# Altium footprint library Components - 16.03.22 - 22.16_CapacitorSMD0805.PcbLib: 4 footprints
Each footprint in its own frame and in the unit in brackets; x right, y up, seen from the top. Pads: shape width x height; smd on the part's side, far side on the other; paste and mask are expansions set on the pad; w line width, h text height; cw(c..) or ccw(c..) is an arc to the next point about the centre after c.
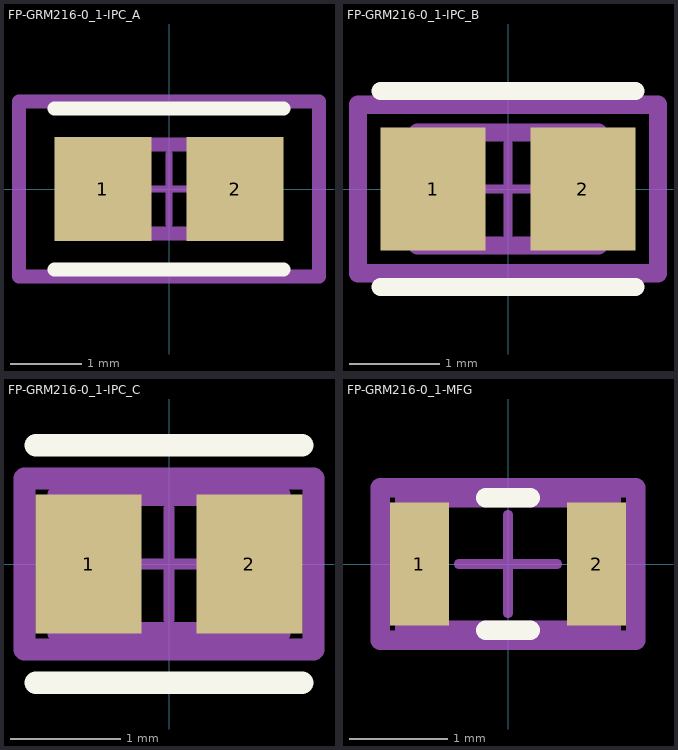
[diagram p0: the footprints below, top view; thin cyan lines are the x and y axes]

## FP-GRM216-0_1-IPC_A [mm]
pads (2):
  rect 1.358x1.461 smd paste+0 mask+0: 1(-0.927,0) 2(0.927,0)
Top Overlay:
  lines w0.2: -1.606,-1.13 1.606,-1.13 ; -1.606,1.13 1.606,1.13
Top Assembly:
  lines w0.2: -2.106,-1.23 2.106,-1.23 2.106,1.23 -2.106,1.23 -2.106,-1.23
  text ".Designator" at 0,0.188 h1
Top 3D Body:
  lines w0.2: -1,-0.625 1,-0.625 1,0.625 -1,0.625 -1,-0.625
Top Courtyard:
  lines w0.2: -2.106,-1.23 2.106,-1.23 2.106,1.23 -2.106,1.23 -2.106,-1.23
Top Component Center:
  lines w0.1: -0.5,0 0.5,0 ; 0,-0.5 0,0.5
3D body "Cap_Murata_GRM2162C1H242JA01D_eec.STEP": height 0.25, standoff 0, extent -2.106,-1.23 2.106,1.23

## FP-GRM216-0_1-IPC_B [mm]
pads (2):
  rect 1.158x1.361 smd paste+0 mask+0: 1(-0.827,0) 2(0.827,0)
Top Overlay:
  lines w0.2: -1.406,-1.08 1.406,-1.08 ; -1.406,1.08 1.406,1.08
Top Assembly:
  lines w0.2: -1.656,-0.93 1.656,-0.93 1.656,0.93 -1.656,0.93 -1.656,-0.93
  text ".Designator" at 0,0.188 h1
Top 3D Body:
  lines w0.2: -1,-0.625 1,-0.625 1,0.625 -1,0.625 -1,-0.625
Top Courtyard:
  lines w0.2: -1.656,-0.93 1.656,-0.93 1.656,0.93 -1.656,0.93 -1.656,-0.93
Top Component Center:
  lines w0.1: -0.5,0 0.5,0 ; 0,-0.5 0,0.5
3D body "Cap_Murata_GRM2162C1H242JA01D_eec.STEP": height 0.25, standoff 0, extent -1.656,-0.93 1.656,0.93

## FP-GRM216-0_1-IPC_C [mm]
pads (2):
  rect 0.958x1.261 smd paste+0 mask+0: 1(-0.727,0) 2(0.727,0)
Top Overlay:
  lines w0.2: -1.206,-1.075 1.206,-1.075 ; -1.206,1.075 1.206,1.075
Top Assembly:
  lines w0.2: -1.306,-0.775 1.306,-0.775 1.306,0.775 -1.306,0.775 -1.306,-0.775
  text ".Designator" at 0,0.188 h1
Top 3D Body:
  lines w0.2: -1,-0.625 1,-0.625 1,0.625 -1,0.625 -1,-0.625
Top Courtyard:
  lines w0.2: -1.306,-0.775 1.306,-0.775 1.306,0.775 -1.306,0.775 -1.306,-0.775
Top Component Center:
  lines w0.1: -0.5,0 0.5,0 ; 0,-0.5 0,0.5
3D body "Cap_Murata_GRM2162C1H242JA01D_eec.STEP": height 0.25, standoff 0, extent -1.306,-0.775 1.306,0.775

## FP-GRM216-0_1-MFG [mm]
pads (2):
  rect 0.6x1.25 smd paste+0 mask+0: 1(-0.9,0) 2(0.9,0)
Top Overlay:
  lines w0.2: -0.225,-0.675 0.225,-0.675 ; -0.225,0.675 0.225,0.675
Top Assembly:
  lines w0.2: -1.3,-0.775 1.3,-0.775 1.3,0.775 -1.3,0.775 -1.3,-0.775
  text ".Designator" at 0,0.188 h1
Top 3D Body:
  lines w0.2: -1.05,-0.675 1.05,-0.675 1.05,0.675 -1.05,0.675 -1.05,-0.675
Top Courtyard:
  lines w0.2: -1.3,-0.775 1.3,-0.775 1.3,0.775 -1.3,0.775 -1.3,-0.775
Top Component Center:
  lines w0.1: -0.5,0 0.5,0 ; 0,-0.5 0,0.5
3D body "Cap_Murata_GRM2162C1H242JA01D_eec.STEP": height 0.25, standoff 0, extent -1.3,-0.775 1.3,0.775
